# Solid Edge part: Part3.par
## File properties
Author: Dan
Template: Normal.par
Last saved by: Dan
Revision: 1
Application: Solid Edge
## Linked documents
Housing.par
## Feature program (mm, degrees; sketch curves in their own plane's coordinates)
part copy "unnamed PartCopy 1"
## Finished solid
Body 1: solid body, 177 faces, 362 edges, 176 vertices.
  Faces by surface: blend 48, cylinder 45, cone 34, plane 25, torus 25
  Edges by curve: circle 208, intersection 106, line 48
Bounding box of the edges (mm; curved faces can reach further): 131.000 x 108.000 x 108.000, from (-85, -54, -54) to (46, 54, 54).
Cylindrical faces by radius (mm): R1 x8, R6.25 x4, R8.25 x8, R9.75 x4, R10 x8, R15.1455 x1, R16 x1, R21 x1, R25.5 x1, R28 x8, R47 x1
Conical faces (half-angle, radius in mm at the cone's reference point): 2 deg R10 x4, 2 deg R14 x4, 2 deg R52.1741 x6, 19.9523 deg R17.8199 x1, 45 deg R21 x1, 45 deg R25.5 x1, 59 deg R8.25 x8, 59 deg R10 x8, 59 deg R16 x1
Toroidal faces (ring radius, tube radius in mm): R0.0916 r44.3294 x1, R8.5924 r2 x4, R12.5105 r1 x4, R15 r3 x1, R24.7008 r1 x1, R44.179 r8 x6, R55.4076 r2 x8
Planar faces by outward normal: +x 8, -x 11, oblique 6
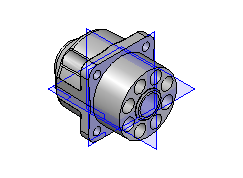
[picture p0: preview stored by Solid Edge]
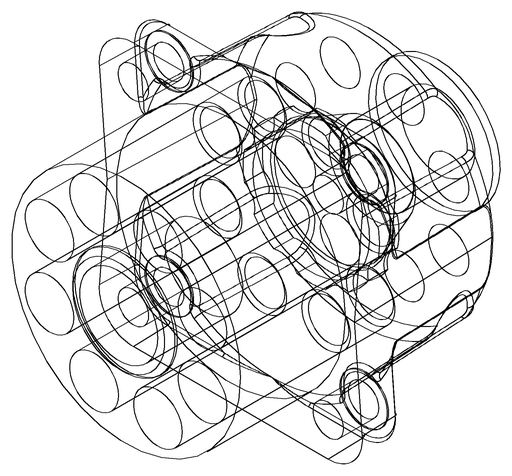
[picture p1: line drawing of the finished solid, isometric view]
